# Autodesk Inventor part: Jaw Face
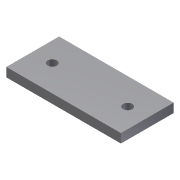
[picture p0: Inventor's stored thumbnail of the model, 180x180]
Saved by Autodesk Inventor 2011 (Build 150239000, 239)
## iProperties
Shininess: 77.0
Length Units: 11269
Angle Units: 11279
Time Units: 11290
Mass Units: 11283
Length Display Precision: 3
Angle Display Precision: 2
Compacted: True
Created: 2002-02
Part Number: Jaw Face
Document SubType Name: Modeling
Designer: ***
Density: 1 g/cm^3
Density: 0.0
Volumn: 0.0
Area: 0.0
PropertySet Name: Model Information
Control State: 0
Master: False
Checked Out: False
Author: ***
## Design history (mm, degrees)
sketch "Sketch1"
  geometry: L1 (-79.661, -8.43)-(-3.661, -8.43); L2 (-3.661, -8.43)-(-3.661, -43.43); L3 (-3.661, -43.43)-(-79.661, -43.43); L4 (-79.661, -43.43)-(-79.661, -8.43); C1 r 3 at (-66.661, -25.93); C2 r 3 at (-16.661, -25.93)
  constraints: 8 end point, 2 centre point, 2 parallel, 1 equal radius, 1 horizontal, 1 perpendicular
  dimensions: "d0" = 76 distance of L2.end L3.end; "d1" = 6 diameter of C1; "d2" = 50 distance of C2.centre C1.centre; "d3" = 35 distance of L1.end L2.end; "d4" = 17.5 distance from line of L3 C2.centre; "d5" = 13 distance from line of L2 C2.centre; "d6" = 13 distance from line of L4 C1.centre
extrude "Extrusion1" new body sketch "Sketch1" stored distance "d7" = 6; taper "d8" = 0 deg
body "Solid1"
